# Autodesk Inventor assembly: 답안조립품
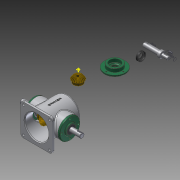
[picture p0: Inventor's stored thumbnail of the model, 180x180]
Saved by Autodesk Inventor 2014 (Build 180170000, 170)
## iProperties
Created: 2015-10
Part Number: 답안조립품
Document SubType Name: Assembly
Designer: Owner
Author: Owner
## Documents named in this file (13)
- C:\Documents and Settings\Owner\바탕 화면\451007V1011\답안조립품.iam
- C:\Documents and Settings\Owner\바탕 화면\451007V1011\본체.ipt
- C:\Documents and Settings\Owner\바탕 화면\451007V1011\오일실.ipt
- C:\Documents and Settings\Owner\바탕 화면\451007V1011\베어링 6203.ipt
- C:\Documents and Settings\Owner\바탕 화면\451007V1011\메인 축.ipt
- 메인 축.ipt
- C:\Documents and Settings\Owner\바탕 화면\451007V1011\메인 베벨기어.ipt
- C:\Documents and Settings\Owner\바탕 화면\451007V1011\커버.ipt
- C:\Documents and Settings\Owner\바탕 화면\451007V1011\키 5x5.ipt
- C:\Documents and Settings\Owner\바탕 화면\451007V1011\서브 베벨기어.ipt
- C:\Documents and Settings\Owner\바탕 화면\451007V1011\키 4x4.ipt
- C:\Documents and Settings\Owner\바탕 화면\451007V1011\서브 축.ipt
- 서브 축.ipt
